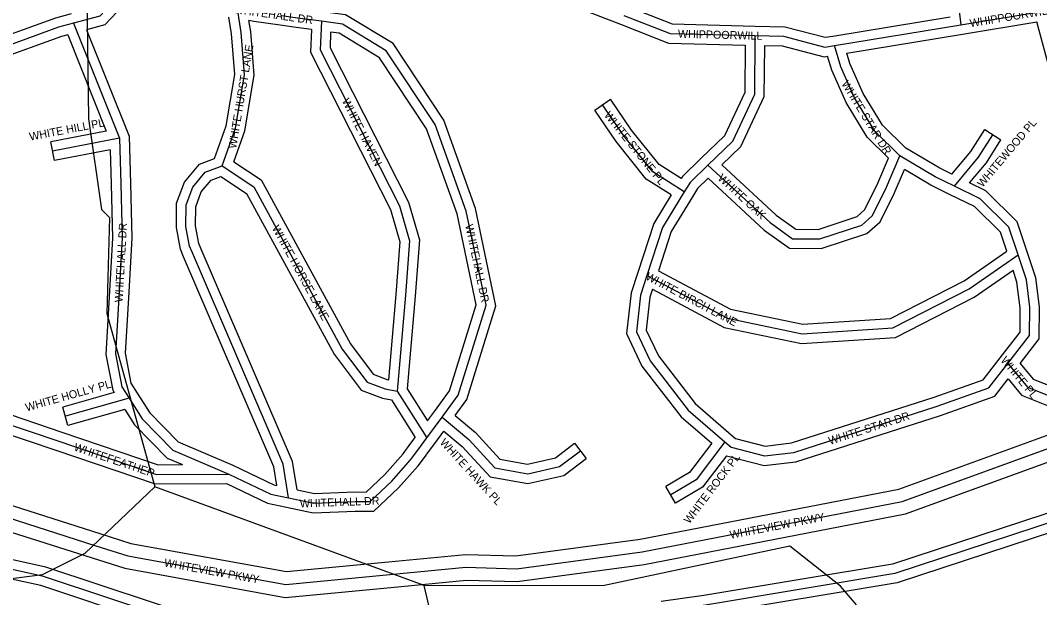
# Model space of a CAD drawing. Extents: x 457167 to 656239, y 1787309 to 1969297.
# Drawn here: x 581357 to 584541, y 1884185 to 1885990 of the extents above; entities that cross this region are included whole.
import ezdxf

# ---------------------------------------------------------------- set-up
doc = ezdxf.new("R2010")
doc.units = 0
for name, color, linetype in [('Level 22', 7, 'Continuous'), ('Level 23', 7, 'Continuous'), ('Level 31', 7, 'Continuous'), ('Level 32', 7, 'Continuous'), ('Level 34', 7, 'Continuous'), ('Level 5', 7, 'Continuous'), ('Level 7', 7, 'Continuous')]:
    doc.layers.add(name, color=color, linetype=linetype)

msp = doc.modelspace()

# ---------------------------------------------------------------- linework, layer by layer
at = {"layer": 'Level 22'}
for p, q in [((581104.294, 1884503.001), (581592.856, 1884347.106)), ((582510.635, 1884256.905), (582748.599, 1884279.706))]:
    msp.add_line(p, q, dxfattribs=at)
for points in [[(582748.599, 1884279.706), (582906.674, 1884275.393), (583299.279, 1884327.71), (584111.624, 1884485.395), (584618.348, 1884669.505)], [(581592.856, 1884347.106), (581692.35, 1884315.632), (582186.139, 1884225.915), (582510.635, 1884256.905)]]:
    msp.add_lwpolyline(points, dxfattribs=at)
at = {"layer": 'Level 23'}
for p, q in [((581116.453, 1884541.11), (581605.016, 1884385.213)), ((581092.134, 1884464.893), (581580.698, 1884308.997)), ((582506.821, 1884296.723), (582747.233, 1884319.758)), ((582514.451, 1884217.086), (582749.968, 1884239.651))]:
    msp.add_line(p, q, dxfattribs=at)
for points in [[(584836.329, 1884791.061), (584639.284, 1885587.767), (584532.513, 1885985.162)], [(582747.233, 1884319.758), (582904.564, 1884315.466), (583292.819, 1884367.204), (584100.916, 1884524.064), (584604.688, 1884707.101)], [(582749.968, 1884239.651), (582908.784, 1884235.32), (583305.737, 1884288.216), (584122.331, 1884446.726), (584632.007, 1884631.908)], [(581604.92, 1884385.244), (581701.995, 1884354.536), (582187.844, 1884266.261), (582506.833, 1884296.725)], [(581580.793, 1884308.967), (581682.704, 1884276.728), (582184.434, 1884185.569), (582514.439, 1884217.085)]]:
    msp.add_lwpolyline(points, dxfattribs=at)
at = {"layer": 'Level 31'}
for p, q in [((584250.699, 1886336.046), (584295.168, 1885975.957)), ((584295.168, 1885975.957), (584564.332, 1886020.891)), ((581522.66, 1885980.713), (581666.339, 1885621.148)), ((583900.012, 1885910.908), (584295.168, 1885975.957)), ((581666.339, 1885621.148), (581457.609, 1885580.841)), ((581696.518, 1884808.355), (581497.293, 1884752.028)), ((582496.199, 1884837.301), (582534.036, 1884830.317)), ((582534.036, 1884830.317), (582626.943, 1884684.676)), ((581189.442, 1884771.559), (581477.098, 1884673.886)), ((582626.943, 1884684.676), (582674.462, 1884749.31)), ((582601.109, 1884649.819), (582626.943, 1884684.676)), ((582575.915, 1884616.051), (582601.109, 1884649.819)), ((581987.025, 1884066.312), (581428.539, 1884251.436))]:
    msp.add_line(p, q, dxfattribs=at)
for points in [[(581743.734, 1886151.178), (581604.763, 1886002.73), (581522.66, 1885980.713)], [(581987.091, 1885535.05), (582028.991, 1885652.421), (582056.996, 1885819.64), (582046.444, 1885951.661), (582034.824, 1886025.866)], [(582297.145, 1885986.797), (582222.422, 1885997.128), (582172.819, 1886004.136)], [(582297.145, 1885986.797), (582293.786, 1885897.348), (582541.544, 1885409.943), (582572.817, 1885300.789), (582559.757, 1885130.268), (582534.036, 1884830.317)], [(582674.462, 1884749.31), (582724.215, 1884817.576), (582811.603, 1885098.859), (582749.843, 1885393.166), (582652.733, 1885664.269), (582499.566, 1885894.757), (582362.648, 1885978.302), (582297.145, 1885986.797)], [(583242.451, 1886005.287), (583387.057, 1885948.64), (583651.351, 1885941.939)], [(581522.66, 1885980.713), (581475.88, 1885968.443), (581270.264, 1885893.949), (581012.269, 1885869.745), (580880.903, 1885865.647)], [(583651.351, 1885941.939), (583649.72, 1885757.941), (583581.369, 1885611.528), (583504.889, 1885537.132)], [(583651.351, 1885941.939), (583741.039, 1885939.946), (583869.469, 1885906.24), (583900.012, 1885910.908)], [(584104.493, 1885566.506), (584026.081, 1885643.387), (583962.67, 1885747.147), (583919.603, 1885844.323), (583900.012, 1885910.908)], [(583430.935, 1885453.641), (583332.139, 1885516.017), (583242.031, 1885628.558), (583175.747, 1885726.145)], [(581666.339, 1885621.148), (581670.507, 1885478.957), (581674.936, 1885308.765), (581664.388, 1885123.694), (581654.174, 1884947.35), (581673.689, 1884844.401), (581696.518, 1884808.355)], [(584274.474, 1885471.63), (584350.346, 1885561.666), (584394.693, 1885632.126)], [(583504.889, 1885537.132), (583699.194, 1885357.477), (583769.069, 1885307.159), (583853.99, 1885306.266), (583985.754, 1885349.646), (584018.253, 1885378.673), (584059.759, 1885460.776), (584104.493, 1885566.506)], [(584274.474, 1885471.63), (584215.052, 1885500.837), (584104.493, 1885566.506)], [(581894.309, 1885262.506), (581885.444, 1885283.251), (581874.118, 1885345.093), (581874.889, 1885412.728), (581895.674, 1885468.323), (581934.253, 1885515.156), (581987.091, 1885535.05)], [(581987.091, 1885535.05), (582085.879, 1885469.761), (582362.54, 1884961.932), (582440.58, 1884858.503), (582496.199, 1884837.301)], [(583504.889, 1885537.132), (583448.804, 1885483.06), (583430.935, 1885453.641)], [(583430.935, 1885453.641), (583362.651, 1885342.137), (583314.012, 1885192.05)], [(584473.802, 1885256.333), (584445.026, 1885343.299), (584355.185, 1885432.201), (584274.474, 1885471.63)], [(582194.629, 1884496.809), (582177.981, 1884601.934), (581894.309, 1885262.506)], [(583314.012, 1885192.05), (583565.34, 1885058.465), (583799.024, 1885009.644), (584082.776, 1885028), (584320.608, 1885150.084), (584473.802, 1885256.333)], [(584441.659, 1884916.757), (584509.576, 1885004.626), (584510.382, 1885092.626), (584499.414, 1885178.101), (584473.802, 1885256.333)], [(583314.012, 1885192.05), (583293.854, 1885130.998), (583281.224, 1885016.114), (583324.304, 1884924.756), (583443.278, 1884771.066), (583557.907, 1884671.568)], [(583557.907, 1884671.568), (583576.959, 1884655.166), (583681.869, 1884628.052), (583772.541, 1884639.148), (584221.298, 1884783.001), (584382.669, 1884840.507), (584441.659, 1884916.757)], [(584441.659, 1884916.757), (584502.585, 1884842.821), (584578.546, 1884812.856)], [(581696.518, 1884808.355), (581737.101, 1884743.909), (581832.964, 1884646.261), (582007.753, 1884571.365)], [(582674.462, 1884749.31), (582757.976, 1884679.326), (582839.227, 1884590.437), (582941.609, 1884572.053), (583041.209, 1884594.401), (583106.193, 1884643.729)], [(581477.098, 1884673.886), (581782.556, 1884570.362), (582007.753, 1884571.365)], [(583557.907, 1884671.568), (583467.661, 1884552.836), (583388.37, 1884506.445)], [(582194.629, 1884496.809), (582273.479, 1884480.651), (582402.308, 1884485.486), (582449.064, 1884485.029), (582516.94, 1884549.259), (582575.915, 1884616.051)], [(582007.753, 1884571.365), (582138.99, 1884508.556), (582194.629, 1884496.809)], [(584894.709, 1882986.781), (585029.663, 1883032.34), (585100.014, 1883061.296), (585147.197, 1883116.841), (585136.602, 1883231.772), (584675.184, 1884453.03), (584088.604, 1884260.347), (583496.795, 1884161.502), (583362.214, 1884142.857)], [(581428.539, 1884251.436), (581213.616, 1884298.416), (581134.711, 1884287.302), (581066.837, 1884225.985), (581057.574, 1884206.003)]]:
    msp.add_lwpolyline(points, dxfattribs=at)
at = {"layer": 'Level 32'}
for p, q in [((583895.139, 1885940.51), (584261.863, 1886000.878)), ((584300.109, 1885946.366), (584532.513, 1885985.162)), ((581563.051, 1885960.482), (581696.171, 1885627.341)), ((581504.637, 1885944.97), (581625.013, 1885643.722)), ((583938.373, 1885886.817), (584300.042, 1885946.355)), ((583150.93, 1885709.288), (583200.564, 1885743.001)), ((581625.012, 1885643.722), (581451.921, 1885610.298)), ((584369.304, 1885648.106), (584420.083, 1885616.144)), ((581463.298, 1885551.384), (581451.921, 1885610.298)), ((581637.385, 1885585.001), (581463.298, 1885551.384)), ((582504.333, 1884866.306), (582506.97, 1884865.82)), ((582564.796, 1884837.881), (582628.698, 1884737.708)), ((581649.654, 1884826.281), (581489.131, 1884780.897)), ((582488.068, 1884808.295), (582515.762, 1884803.182)), ((581199.087, 1884799.966), (581486.744, 1884702.294)), ((581505.456, 1884723.158), (581489.131, 1884780.897)), ((582515.761, 1884803.182), (582590.546, 1884685.95)), ((581179.797, 1884743.151), (581467.453, 1884645.478)), ((581683.089, 1884773.38), (581505.456, 1884723.158)), ((582628.698, 1884737.709), (582650.292, 1884767.081)), ((582577.064, 1884667.759), (582590.546, 1884685.95)), ((582651.114, 1884666.905), (582679.697, 1884705.781)), ((582552.609, 1884634.981), (582577.064, 1884667.759)), ((582625.212, 1884631.956), (582651.045, 1884666.813)), ((583088.054, 1884667.626), (583124.332, 1884619.832)), ((582599.223, 1884597.118), (582625.154, 1884631.878)), ((583403.52, 1884480.55), (583373.221, 1884532.339)), ((581994.122, 1884095.566), (581436.484, 1884280.407)), ((581951.402, 1884046.514), (581420.594, 1884222.462))]:
    msp.add_line(p, q, dxfattribs=at)
for points in [[(582360.458, 1886414.422), (582839.123, 1886156.28), (583030.399, 1886056.53), (583231.461, 1885977.372)], [(581749.516, 1886113.455), (581620.809, 1885975.971), (581563.052, 1885960.483)], [(582715.22, 1884754.296), (582751.389, 1884803.925), (582842.564, 1885097.396), (582778.781, 1885401.342), (582679.743, 1885677.827), (582520.871, 1885916.901), (582372.83, 1886007.234), (582301.004, 1886016.549)], [(583284.09, 1886021.196), (583393.089, 1885978.496), (583652.111, 1885971.93)], [(581515.049, 1886009.732), (581466.947, 1885997.116), (581263.648, 1885923.461), (581010.399, 1885899.701), (580879.968, 1885895.633)], [(581963.511, 1885558.226), (581999.842, 1885660.001), (582026.795, 1885820.941), (582016.63, 1885948.141), (582008.483, 1886000.171)], [(582023.253, 1885547.111), (582058.139, 1885644.841), (582087.196, 1885818.337), (582076.259, 1885955.181), (582070.967, 1885988.984)], [(582168.547, 1885974.441), (582086.024, 1885986.312), (582070.967, 1885988.984)], [(582266.148, 1885960.796), (582218.269, 1885967.416), (582168.622, 1885974.431)], [(582266.149, 1885960.796), (582263.515, 1885890.695), (582513.497, 1885398.914), (582542.492, 1885297.706), (582529.855, 1885132.696), (582506.971, 1884865.821)], [(582325.891, 1885952.816), (582324.058, 1885904.002), (582569.593, 1885420.971), (582603.141, 1885303.871), (582589.659, 1885127.841), (582564.796, 1884837.881)], [(582650.218, 1884766.981), (582697.041, 1884831.227), (582780.642, 1885100.321), (582720.905, 1885384.988), (582625.723, 1885650.71), (582478.261, 1885872.612), (582352.466, 1885949.371), (582325.891, 1885952.816)], [(583231.509, 1885977.353), (583381.024, 1885918.782), (583621.091, 1885912.695)], [(583652.017, 1885971.932), (583745.238, 1885969.86), (583871.076, 1885936.835), (583895.139, 1885940.51)], [(581504.637, 1885944.969), (581484.814, 1885939.771), (581276.882, 1885864.437), (581014.14, 1885839.787), (580914.203, 1885836.67)], [(583621.091, 1885912.695), (583619.779, 1885764.726), (583556.51, 1885629.2), (583483.971, 1885558.637)], [(583681.081, 1885911.268), (583679.661, 1885751.157), (583606.229, 1885593.856), (583548.484, 1885537.684)], [(583681.081, 1885911.268), (583736.842, 1885910.031), (583867.862, 1885875.645), (583878.632, 1885877.291)], [(584068.906, 1885559.385), (584002.422, 1885624.569), (583936.043, 1885733.187), (583891.377, 1885833.966), (583878.632, 1885877.291)], [(584122.919, 1885590.456), (584049.74, 1885662.205), (583989.298, 1885761.108), (583947.828, 1885854.679), (583938.373, 1885886.816)], [(583421.141, 1885495.304), (583352.412, 1885538.698), (583266.186, 1885646.39), (583200.564, 1885743.001)], [(583389.897, 1885444.071), (583311.867, 1885493.336), (583217.876, 1885610.727), (583150.93, 1885709.288)], [(584266.652, 1885508.902), (584326.064, 1885579.408), (584369.304, 1885648.106)], [(581696.172, 1885627.342), (581700.495, 1885479.787), (581704.959, 1885308.301), (581694.339, 1885121.972), (581684.338, 1884949.305), (581702.097, 1884855.614), (581721.863, 1884824.407)], [(584322.197, 1885481.705), (584374.627, 1885543.924), (584420.083, 1885616.144)], [(581637.385, 1885585.001), (581640.518, 1885478.128), (581644.914, 1885309.229), (581634.437, 1885125.416), (581624.01, 1884945.395), (581645.28, 1884833.186), (581649.654, 1884826.281)], [(584266.652, 1885508.903), (584229.351, 1885527.237), (584122.919, 1885590.456)], [(581866.721, 1885250.719), (581856.539, 1885274.548), (581844.087, 1885342.537), (581844.95, 1885418.318), (581869.329, 1885483.528), (581916.189, 1885540.411), (581963.511, 1885558.227)], [(582023.252, 1885547.111), (582108.65, 1885490.671), (582387.824, 1884978.231), (582459.33, 1884883.462), (582504.334, 1884866.306)], [(583484.067, 1885558.731), (583425.182, 1885501.959), (583421.141, 1885495.303)], [(583548.484, 1885537.684), (583718.214, 1885380.751), (583778.889, 1885337.058), (583849.333, 1885336.317), (583970.432, 1885376.186), (583994.038, 1885397.27), (584032.527, 1885473.403), (584068.906, 1885559.383)], [(583505.32, 1885495.874), (583680.174, 1885334.205), (583759.25, 1885277.26), (583858.649, 1885276.214), (584001.075, 1885323.105), (584042.468, 1885360.076), (584086.993, 1885448.147), (584118.729, 1885523.157)], [(584261.24, 1885444.706), (584200.754, 1885474.437), (584118.729, 1885523.157)], [(581921.896, 1885274.293), (581914.35, 1885291.955), (581904.149, 1885347.648), (581904.828, 1885407.138), (581922.019, 1885453.119), (581952.318, 1885489.9), (581983.329, 1885501.575)], [(581983.329, 1885501.575), (582063.107, 1885448.85), (582337.256, 1884945.632), (582421.83, 1884833.544), (582488.067, 1884808.295)], [(583505.321, 1885495.875), (583472.426, 1885464.161), (583456.577, 1885438.066)], [(584502.284, 1885265.758), (584471.246, 1885359.559), (584372.783, 1885456.993), (584322.197, 1885481.705)], [(583389.897, 1885444.071), (583335.209, 1885354.771), (583285.473, 1885201.299)], [(584438.275, 1885268.202), (584418.806, 1885327.038), (584337.588, 1885407.409), (584261.305, 1885444.673)], [(583456.519, 1885437.972), (583390.094, 1885329.504), (583350.308, 1885206.733)], [(582221.01, 1884522.026), (582207.027, 1884610.328), (581921.874, 1885274.344)], [(583350.308, 1885206.732), (583575.653, 1885086.959), (583801.163, 1885039.846), (584074.619, 1885057.536), (584305.141, 1885175.867), (584438.274, 1885268.201)], [(584480.04, 1884917.355), (584539.484, 1884994.262), (584540.399, 1885094.405), (584528.81, 1885184.737), (584502.313, 1885265.668)], [(582158.182, 1884535.166), (582148.936, 1884593.54), (581866.743, 1885250.668)], [(583285.524, 1885201.456), (583264.378, 1885137.411), (583250.479, 1885010.977), (583298.569, 1884908.989), (583421.372, 1884750.355), (583517.011, 1884667.339)], [(583331.346, 1885148.861), (583555.029, 1885029.971), (583796.887, 1884979.442), (584090.932, 1884998.464), (584336.074, 1885124.301), (584457.819, 1885208.736)], [(584417.923, 1884935.105), (584479.669, 1885014.991), (584480.364, 1885090.846), (584470.019, 1885171.466), (584457.818, 1885208.736)], [(583331.346, 1885148.861), (583323.33, 1885124.586), (583311.971, 1885021.251), (583350.037, 1884940.521), (583465.184, 1884791.778), (583577.572, 1884694.224)], [(583577.572, 1884694.224), (583591.234, 1884682.464), (583683.869, 1884658.521), (583766.083, 1884668.582), (584211.68, 1884811.423), (584364.319, 1884865.816), (584417.931, 1884935.116)], [(584480.04, 1884917.355), (584520.807, 1884867.883), (584589.554, 1884840.763)], [(583562.499, 1884628.029), (583562.684, 1884627.869), (583679.869, 1884597.583), (583778.999, 1884609.714), (584230.915, 1884754.58), (584401.019, 1884815.197), (584442.399, 1884868.684)], [(584442.399, 1884868.684), (584484.364, 1884817.759), (584567.537, 1884784.948)], [(581721.904, 1884824.341), (581760.769, 1884762.625), (581850.223, 1884671.505), (582020.143, 1884598.695)], [(581683.089, 1884773.381), (581713.434, 1884725.194), (581815.704, 1884621.018), (581863.072, 1884600.721)], [(582715.22, 1884754.296), (582778.774, 1884701.04), (582854.521, 1884618.171), (582940.95, 1884602.652), (583028.27, 1884622.246), (583088.054, 1884667.626)], [(581486.727, 1884702.3), (581787.437, 1884600.385), (581863.072, 1884600.721)], [(582679.697, 1884705.781), (582737.179, 1884657.613), (582823.933, 1884562.703), (582942.268, 1884541.454), (583054.149, 1884566.557), (583124.332, 1884619.832)], [(583517.011, 1884667.339), (583447.376, 1884575.726), (583373.221, 1884532.339)], [(581467.469, 1884645.473), (581777.675, 1884540.34), (582001.009, 1884541.333)], [(582221.01, 1884522.026), (582275.963, 1884510.766), (582401.891, 1884515.492), (582437.243, 1884515.146), (582495.343, 1884570.125), (582552.609, 1884634.981)], [(583562.498, 1884628.029), (583487.946, 1884529.945), (583403.52, 1884480.55)], [(582020.143, 1884598.694), (582148.702, 1884537.168), (582158.182, 1884535.166)], [(582188.608, 1884467.419), (582270.995, 1884450.536), (582402.724, 1884455.479), (582460.884, 1884454.911), (582538.538, 1884528.392), (582599.223, 1884597.118)], [(582001.008, 1884541.333), (582129.279, 1884479.945), (582188.433, 1884467.456)], [(584904.304, 1882958.356), (585040.181, 1883004.226), (585118.166, 1883036.325), (585178.228, 1883107.033), (585166.102, 1883238.573), (584693.099, 1884490.492), (584081.411, 1884289.562), (583492.264, 1884191.162), (583358.096, 1884172.574)], [(584914.499, 1883025.124), (585019.145, 1883060.453), (585081.863, 1883086.267), (585116.165, 1883126.65), (585107.101, 1883224.971), (584657.268, 1884415.567), (584095.799, 1884231.132), (583501.325, 1884131.843), (583399.413, 1884117.723)], [(581436.484, 1884280.407), (581214.763, 1884328.874), (581121.422, 1884315.728), (581042.191, 1884244.15), (581030.484, 1884218.894)], [(581420.595, 1884222.462), (581212.469, 1884267.957), (581147.999, 1884258.877), (581091.484, 1884207.821), (581084.664, 1884193.112)]]:
    msp.add_lwpolyline(points, dxfattribs=at)
at = {"layer": 'Level 5'}
for p, q in [((582618.126, 1884222.357), (581776.49, 1884531.68)), ((582750.925, 1883671.995), (582618.126, 1884222.357))]:
    msp.add_line(p, q, dxfattribs=at)
msp.add_lwpolyline([(581100.924, 1884215.649), (581426.079, 1884256.971), (581559.519, 1884323.534), (581776.49, 1884531.68)], dxfattribs=at)
at = {"layer": 'Level 7'}
for points in [[(581312.606, 1887291.545), (581379.139, 1887149.761), (581437.431, 1887091.341), (581445.702, 1887016.278), (581553.876, 1886849.455), (581569.312, 1885682.327), (581610.706, 1885398.861), (581635.687, 1885373.82), (581627.02, 1885073.712), (581776.49, 1884531.68)], [(582750.925, 1883671.995), (583184.609, 1883854.931), (583726.595, 1883979.427), (583943.466, 1884095.871), (583968.546, 1884162.562), (583918.594, 1884220.954), (583760.33, 1884346.156), (583176.664, 1884221.77), (582618.126, 1884222.357)]]:
    msp.add_lwpolyline(points, dxfattribs=at)

# ---------------------------------------------------------------- texts
at = {"layer": 'Level 34'}
for s, rotation, p in [('WHITEHALL DR', 351.814211, (582022.934, 1886013.068)), ('WHIPPOORWILL', 9.477028, (584325.095, 1885968.281)), ('WHIPPOORWILL', 358.547508, (583410.733, 1885935.536)), ('WHITE HURST LANE', 80.491875, (582030.739, 1885587.191)), ('WHITE STAR DR', 301.429839, (583920.889, 1885791.546)), ('WHITE HAVEN', 296.944664, (582360.709, 1885738.109)), ('WHITE STONE PL', 308.683025, (583179.083, 1885692.689)), ('WHITE HILL PL', 10.929283, (581387.311, 1885613.441)), ('WHITEWOOD PL', 49.878292, (584362.317, 1885465.888)), ('WHITE OAK', 317.243158, (583533.544, 1885493.614)), ('WHITEHALL DR', 86.736969, (581675.984, 1885107.505)), ('WHITE HORSE LANE', 298.580828, (582142.038, 1885340.551)), ('WHITEHALL DR', 281.850914, (582746.271, 1885349.328)), ('WHITE BIRCH LANE', 332.008511, (583307.823, 1885181.184)), ('WHITE PL', 309.489542, (584417.71, 1884926.166)), ('WHITE HOLLY PL', 15.786714, (581376.287, 1884766.907)), ('WHITE STAR DR', 17.773328, (583886.012, 1884662.397)), ('WHITE HAWK PL', 312.429269, (582665.521, 1884668.559)), ('WHITEFEATHER', 341.277539, (581522.009, 1884645.467)), ('WHITE ROCK PL', 52.761617, (583446.969, 1884413.856)), ('WHITEHALL DR', 2.148664, (582230.249, 1884466.521)), ('WHITEVIEW PKWY', 10.984703, (583575.654, 1884368.625)), ('WHITEVIEW PKWY', 349.701978, (581804.534, 1884282.546))]:
    msp.add_text(s, height=25, rotation=rotation, dxfattribs=at).set_placement(p)

doc.saveas('drawing.dxf')
